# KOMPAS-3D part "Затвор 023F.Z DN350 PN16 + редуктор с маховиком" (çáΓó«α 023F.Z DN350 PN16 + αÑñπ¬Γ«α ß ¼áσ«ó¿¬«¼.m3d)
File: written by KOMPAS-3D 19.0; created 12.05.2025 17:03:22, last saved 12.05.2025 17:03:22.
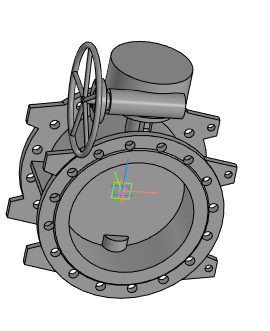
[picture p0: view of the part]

Document properties: Полное имя файла: Затвор 023F.Z DN350 PN16 + редуктор с маховиком.a3d

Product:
- Part/product: Затвор 023F.Z DN350 PN16 + редуктор с маховиком
    Масса: 169.871

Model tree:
1. Операция без истории:1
